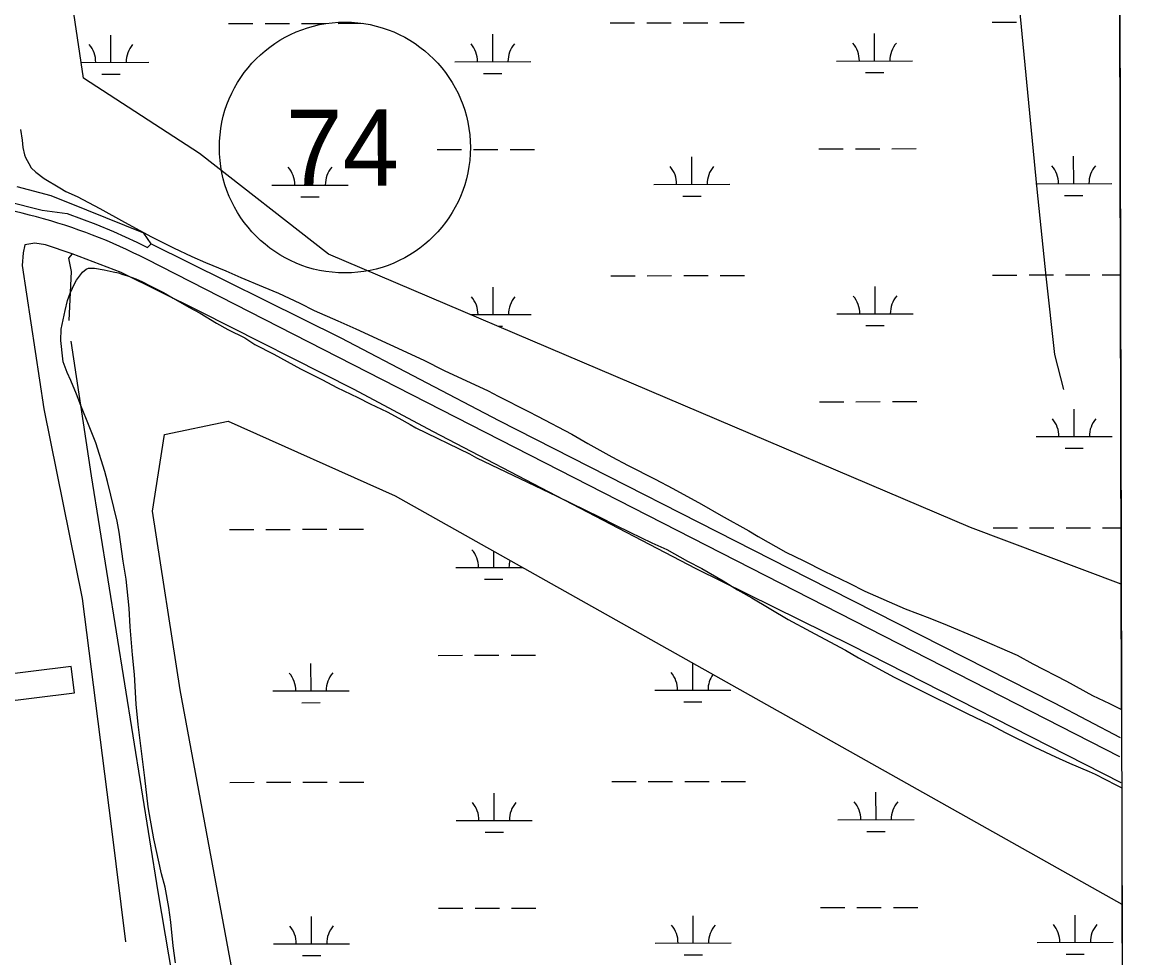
# Model space of a CAD drawing. Extents: x 3329332 to 3367211, y 631066 to 656469.
# Drawn here: x 3363578 to 3365030, y 639263 to 640494 of the extents above; entities that cross this region are included whole.
import ezdxf

# ---------------------------------------------------------------- set-up
doc = ezdxf.new("R2010")
doc.units = 0
for name, color, linetype in [('V-BLDG-OTLN', 7, 'Continuous'), ('V-GRID-FRAM', 7, 'Continuous'), ('V-ROAD-CNTR', 7, 'Continuous'), ('V-ROAD-IDEN', 7, 'Continuous'), ('V-SITE-VEGE', 7, 'Continuous'), ('V-TOPO-SHOR', 7, 'Continuous'), ('V-WETL-SWMP', 7, 'Continuous')]:
    doc.layers.add(name, color=color, linetype=linetype)

msp = doc.modelspace()

# ---------------------------------------------------------------- linework, layer by layer
at = {"layer": 'V-BLDG-OTLN'}
msp.add_lwpolyline([(3363539.6, 639633.8), (3363543.9, 639599.1), (3363646.9, 639612), (3363642.5, 639646.7)], close=True, dxfattribs=at)
at = {"layer": 'V-GRID-FRAM'}
msp.add_lwpolyline([(3333429.9, 654632), (3364987.9, 654691.7), (3365030.2, 636507.7), (3333456.4, 636448), (3333429.9, 654632)], dxfattribs=at)
at = {"layer": 'V-ROAD-CNTR'}
msp.add_lwpolyline([(3365020.7, 639527.6), (3363741.5, 640182.1)], dxfattribs=at)
msp.add_arc((3363407.1, 639530.1), 732.8, 62.8442, 87.1319, dxfattribs=at)
at = {"layer": 'V-ROAD-IDEN'}
msp.add_circle((3364002.2, 640329.1), 165, dxfattribs=at)
msp.add_circle((3364002.2, 640329.1), 165, dxfattribs=at)
at = {"layer": 'V-SITE-VEGE'}
for p, q in [((3363657.1, 640165.1), (3363662.2, 640168.9)), ((3363662.2, 640168.9), (3363665, 640170.5)), ((3363665, 640170.5), (3363672.9, 640170.3)), ((3363672.9, 640170.3), (3363685.7, 640168.4)), ((3363685.7, 640168.4), (3363697.4, 640165.4)), ((3363647.3, 640150.7), (3363649.6, 640154.6)), ((3363649.6, 640154.6), (3363657.1, 640165.1)), ((3363697.4, 640165.4), (3363704.6, 640164.1)), ((3363704.6, 640164.1), (3363710.2, 640162.3)), ((3363710.2, 640162.3), (3363716.3, 640160.5)), ((3363716.3, 640160.5), (3363727.4, 640156.4)), ((3363727.4, 640156.4), (3363736.2, 640152.3)), ((3363640.9, 640137.4), (3363647.3, 640150.7)), ((3363736.2, 640152.3), (3363746.2, 640147)), ((3363746.2, 640147), (3363763.9, 640138.3)), ((3363763.9, 640138.3), (3363776.6, 640130.8)), ((3363634.3, 640114.7), (3363637.4, 640128)), ((3363637.4, 640128), (3363640.9, 640137.4)), ((3363776.6, 640130.8), (3363797, 640119.2)), ((3363629.3, 640090.2), (3363634.3, 640114.7)), ((3363797, 640119.2), (3363812, 640111.1)), ((3363812, 640111.1), (3363833.5, 640098.3)), ((3363833.5, 640098.3), (3363848.4, 640089.6)), ((3363629, 640075.1), (3363629.3, 640090.2)), ((3363848.4, 640089.6), (3363870.5, 640078.6)), ((3363631.3, 640051), (3363629, 640075.1)), ((3363870.5, 640078.6), (3363883.8, 640069.9)), ((3363883.8, 640069.9), (3363908.7, 640057.1)), ((3363908.7, 640057.1), (3363944, 640038)), ((3363631.8, 640047.1), (3363631.3, 640051)), ((3363637.1, 640033), (3363631.8, 640047.1)), ((3363944, 640038), (3363972.8, 640023.4)), ((3363641.9, 640022.8), (3363637.1, 640033)), ((3363649.4, 640004.8), (3363641.9, 640022.8)), ((3363972.8, 640023.4), (3363991.6, 640013.5)), ((3363991.6, 640013.5), (3364019.3, 640000.1)), ((3363655.2, 639989.6), (3363649.4, 640004.8)), ((3364019.3, 640000.1), (3364035.3, 639992)), ((3363665.9, 639962.6), (3363655.2, 639989.6)), ((3364035.3, 639992), (3364058, 639981.4)), ((3364058, 639981.4), (3364073, 639973.3)), ((3364073, 639973.3), (3364087.9, 639964.6)), ((3364087.9, 639964.6), (3364095.6, 639960.6)), ((3363674.9, 639940.6), (3363665.9, 639962.6)), ((3364095.6, 639960.6), (3364165.9, 639926.2)), ((3363686.5, 639902.9), (3363674.9, 639940.6)), ((3364165.9, 639926.2), (3364175.3, 639920.9)), ((3364175.3, 639920.9), (3364281, 639870.7)), ((3363690.1, 639890), (3363686.5, 639902.9)), ((3363703, 639837.7), (3363690.1, 639890)), ((3364281, 639870.7), (3364337.5, 639842.8)), ((3363705.5, 639823.1), (3363703, 639837.7)), ((3364337.5, 639842.8), (3364357.9, 639832.3)), ((3363710.9, 639785), (3363705.5, 639823.1)), ((3364357.9, 639832.3), (3364376.8, 639823)), ((3364376.8, 639823), (3364405.5, 639809)), ((3364405.5, 639809), (3364425.5, 639800.2)), ((3364425.5, 639800.2), (3364452.6, 639785.1)), ((3363714.9, 639761.5), (3363710.9, 639785)), ((3364452.6, 639785.1), (3364471.4, 639775.2)), ((3364471.4, 639775.2), (3364499.5, 639759)), ((3363718.6, 639723.4), (3363714.9, 639761.5)), ((3364499.5, 639759), (3364518.3, 639747.4)), ((3364518.3, 639747.4), (3364537.1, 639737)), ((3364537.1, 639737), (3364585.1, 639708.1)), ((3363719.8, 639698.8), (3363718.6, 639723.4)), ((3364585.1, 639708.1), (3364614.4, 639692.4)), ((3363722.9, 639661.8), (3363719.8, 639698.8)), ((3364614.4, 639692.4), (3364633.2, 639682.5)), ((3364633.2, 639682.5), (3364660.3, 639668)), ((3363725.8, 639636.1), (3363722.9, 639661.8)), ((3364660.3, 639668), (3364677.5, 639658.1)), ((3364677.5, 639658.1), (3364724.4, 639632.6)), ((3363727.8, 639596.9), (3363725.8, 639636.1)), ((3364724.4, 639632.6), (3364753.2, 639618)), ((3364753.2, 639618), (3364820.2, 639584.8)), ((3363730.6, 639570), (3363727.8, 639596.9)), ((3364820.2, 639584.8), (3364850.6, 639570.2)), ((3363739.2, 639500), (3363730.6, 639570)), ((3364850.6, 639570.2), (3364871.1, 639559.2)), ((3364871.1, 639559.2), (3364909.3, 639540.5)), ((3364909.3, 639540.5), (3364936.4, 639527.7)), ((3364936.4, 639527.7), (3364954.7, 639519.5)), ((3364954.7, 639519.5), (3364980.7, 639508.3)), ((3363743.5, 639461.9), (3363739.2, 639500)), ((3364980.7, 639508.3), (3364988.5, 639504.8)), ((3364988.5, 639504.8), (3365015.6, 639490.9)), ((3365015.6, 639490.9), (3365023.3, 639487)), ((3365023.3, 639487), (3365030.2, 636507.7)), ((3363745.5, 639451.8), (3363743.5, 639461.9)), ((3363751, 639419.8), (3363745.5, 639451.8)), ((3363761.2, 639373.8), (3363751, 639419.8)), ((3363765.9, 639356.4), (3363761.2, 639373.8)), ((3363771, 639329.4), (3363765.9, 639356.4)), ((3363773.4, 639310.4), (3363771, 639329.4)), ((3363776.6, 639279), (3363773.4, 639310.4)), ((3363779.5, 639256.6), (3363776.6, 639279))]:
    msp.add_line(p, q, dxfattribs=at)
for points in [[(3365023, 639590.1), (3365016.6, 642361.5), (3364994, 642372.5), (3364958.7, 642392.2), (3364915.6, 642417.7), (3364886.3, 642435.6)], [(3363576, 640352.8), (3363577.9, 640338.8), (3363578.8, 640329.3), (3363580.9, 640319.7), (3363582.5, 640315.8), (3363586.8, 640307.9), (3363590, 640302.2), (3363596.1, 640296.5), (3363607.1, 640288.5), (3363627.5, 640276.3), (3363635.2, 640271.1), (3363650.2, 640264.7), (3363680.1, 640249), (3363712.7, 640231), (3363748, 640211.8), (3363776.8, 640197.3), (3363801.2, 640185.6), (3363818.9, 640178), (3363845.5, 640166.8), (3363865.4, 640158), (3363894.8, 640145.7), (3363914.8, 640137.5), (3363943, 640124.6), (3363961.8, 640114.7), (3363992.8, 640101.2), (3364016.7, 640090.7), (3364105.8, 640049.2), (3364132.9, 640035.8), (3364190.5, 640008.9), (3364203.8, 640002), (3364243.6, 639982.1), (3364255.2, 639975.8), (3364300.6, 639951.9), (3364321.6, 639939.8), (3364353.1, 639922.4), (3364374.6, 639910.7), (3364410, 639892.7), (3364433.3, 639880.5), (3364470.8, 639860.2), (3364496.8, 639845.1), (3364533.3, 639824.8), (3364545.4, 639817.3), (3364581.9, 639797), (3364605.7, 639785.3), (3364632.3, 639771.9), (3364664.9, 639756.2), (3364685.9, 639745.7), (3364738.6, 639722.3), (3364771.3, 639709.9), (3364794, 639701), (3364829.5, 639685.8), (3364886, 639661.2), (3364906.4, 639650.1), (3364950.7, 639627.4), (3364985, 639608.3), (3365007.1, 639597.8), (3365023, 639590.1)]]:
    msp.add_lwpolyline(points, dxfattribs=at)
at = {"layer": 'V-TOPO-SHOR'}
for points in [[(3363842.9, 641705.6), (3363751.5, 641522), (3363763.2, 641395.9), (3363774.9, 641315.6), (3363820.9, 641201.1), (3363855.5, 641109.4), (3363947.4, 641017.9), (3364176.8, 640972.5), (3364371.8, 640927), (3364532.4, 640881.4), (3364693, 640824.4), (3364807.9, 640687), (3364888.5, 640515.2), (3364911.8, 640274.5), (3364923.5, 640159.9), (3364935.2, 640056.7), (3364946.7, 640010.9)], [(3363557.4, 640258.4), (3363604.4, 640246.8), (3363637.2, 640242.2), (3363674.7, 640228.2), (3363698.2, 640218.8), (3363728.7, 640204.8), (3363742.8, 640197.8), (3363747.5, 640202.5), (3363738.1, 640216.6), (3363663, 640246.9), (3363616, 640265.6), (3363571.5, 640277.2)], [(3363643.7, 640189.4), (3363608.5, 640201.1), (3363594.5, 640203.4), (3363581.6, 640201), (3363579.3, 640190.5), (3363578.1, 640174.1), (3363606.6, 639985.4)], [(3363747.5, 640202.5), (3363996.9, 640078.7), (3364204.6, 639970.1), (3364610.6, 639763.3), (3364934.5, 639598.6), (3365021.4, 639553.1)], [(3365022.7, 639493.3), (3364668.3, 639674.3), (3364464.1, 639774.8), (3364117.8, 639955.8), (3364014.6, 640010.8), (3363811.5, 640113.5), (3363708.3, 640164.9), (3363643.7, 640189.4), (3363639.1, 640183.6), (3363642.6, 640166), (3363639.2, 640101.5)], [(3364077.4, 637523.9), (3363955.4, 638180.4), (3363913.4, 638425.6), (3363756.9, 639350), (3363669, 639897.1), (3363642.3, 640074.4)], [(3363606.6, 639985.4), (3363656.7, 639736), (3363695.1, 639436.5), (3363713.8, 639284.3)]]:
    msp.add_lwpolyline(points, dxfattribs=at)
at = {"layer": 'V-WETL-SWMP'}
for p, q in [((3365016.6, 642324.6), (3365022.6, 639754.6)), ((3363658.7, 640420.2), (3363604, 640788.8)), ((3363849.2, 640492.1), (3363881.2, 640492.2)), ((3363897.2, 640492.2), (3363929.2, 640492.3)), ((3363945.2, 640492.3), (3363977.2, 640492.4)), ((3363993.2, 640492.4), (3364025.2, 640492.5)), ((3364351.1, 640493.1), (3364383.1, 640493.1)), ((3364399.1, 640493.2), (3364431.1, 640493.2)), ((3364447.1, 640493.3), (3364479.1, 640493.3)), ((3364495.1, 640493.4), (3364527.1, 640493.4)), ((3364853, 640494), (3364885, 640494.1)), ((3363694.7, 640441.1), (3363694.6, 640477.1)), ((3364196.6, 640442.1), (3364196.5, 640478.1)), ((3364698.5, 640443), (3364698.4, 640479)), ((3363655.6, 640441), (3363744.7, 640441.2)), ((3364146.6, 640442), (3364246.6, 640442.1)), ((3364648.5, 640442.9), (3364748.5, 640443.1)), ((3363811, 640321.2), (3363658.7, 640420.2)), ((3363682.7, 640425.7), (3363706.7, 640425.7)), ((3364184.6, 640426.6), (3364208.6, 640426.6)), ((3364686.5, 640427.6), (3364710.5, 640427.6)), ((3364625.3, 640327.4), (3364657.3, 640327.5)), ((3364673.3, 640327.5), (3364705.3, 640327.6)), ((3364721.3, 640327.6), (3364753.3, 640327.7)), ((3363980.5, 640188.9), (3363811, 640321.2)), ((3363956.4, 640279.7), (3363956.4, 640315.7)), ((3364123.4, 640326.5), (3364155.4, 640326.5)), ((3364171.4, 640326.6), (3364203.4, 640326.6)), ((3364219.4, 640326.7), (3364251.4, 640326.7)), ((3364458.3, 640280.7), (3364458.3, 640316.7)), ((3364960.3, 640281.6), (3364960.2, 640317.6)), ((3363906.4, 640279.6), (3364006.4, 640279.8)), ((3364408.3, 640280.6), (3364508.3, 640280.8)), ((3364910.3, 640281.5), (3365010.3, 640281.7)), ((3363944.5, 640264.3), (3363968.5, 640264.3)), ((3364446.4, 640265.2), (3364470.4, 640265.3)), ((3364948.3, 640266.2), (3364972.3, 640266.2)), ((3364824.6, 639829.4), (3363980.5, 640188.9)), ((3364351.7, 640160.4), (3364383.7, 640160.5)), ((3364399.7, 640160.5), (3364431.7, 640160.6)), ((3364447.7, 640160.6), (3364479.7, 640160.7)), ((3364495.7, 640160.7), (3364527.7, 640160.7)), ((3364853.6, 640161.4), (3364885.6, 640161.4)), ((3364901.6, 640161.5), (3364933.6, 640161.5)), ((3364949.6, 640161.5), (3364981.6, 640161.6)), ((3364997.6, 640161.6), (3365021.7, 640161.7)), ((3364197.2, 640109.4), (3364197.2, 640145.4)), ((3364699.1, 640110.3), (3364699.1, 640146.3)), ((3364167.4, 640109.3), (3364247.2, 640109.5)), ((3364649.1, 640110.2), (3364749.1, 640110.4)), ((3364687.2, 640094.9), (3364711.2, 640094.9)), ((3364203.5, 640094), (3364209.3, 640094)), ((3364626, 639994.8), (3364658, 639994.8)), ((3364674, 639994.8), (3364706, 639994.9)), ((3364722, 639994.9), (3364754, 639995)), ((3364960.9, 639949), (3364960.8, 639985)), ((3363764.9, 639951.5), (3363848.7, 639969.2)), ((3363848.7, 639969.2), (3364068.2, 639871.1)), ((3363749.2, 639850.6), (3363764.9, 639951.5)), ((3364910.9, 639948.9), (3365010.9, 639949.1)), ((3364948.9, 639933.5), (3364972.9, 639933.6)), ((3364068.2, 639871.1), (3365023.6, 639333.8)), ((3363785.5, 639616), (3363749.2, 639850.6)), ((3363850.5, 639826.8), (3363882.5, 639826.9)), ((3363898.5, 639826.9), (3363930.5, 639826.9)), ((3363946.5, 639827), (3363978.5, 639827)), ((3363994.5, 639827.1), (3364026.5, 639827.1)), ((3365022.6, 639754.6), (3364824.6, 639829.4)), ((3364854.3, 639828.7), (3364886.3, 639828.7)), ((3364902.3, 639828.8), (3364934.3, 639828.8)), ((3364950.3, 639828.9), (3364982.3, 639828.9)), ((3364998.3, 639829), (3365022.5, 639829)), ((3364197.9, 639776.7), (3364197.8, 639798.1)), ((3364147.9, 639776.6), (3364235.8, 639776.8)), ((3364185.9, 639761.3), (3364209.9, 639761.3)), ((3364124.7, 639661.1), (3364156.7, 639661.2)), ((3364172.7, 639661.2), (3364204.7, 639661.3)), ((3364220.7, 639661.3), (3364252.7, 639661.4)), ((3363957.7, 639614.4), (3363957.6, 639650.4)), ((3364459.6, 639615.3), (3364459.5, 639651)), ((3364161.7, 637589.5), (3363785.5, 639616)), ((3363907.7, 639614.3), (3364007.7, 639614.5)), ((3364409.6, 639615.2), (3364509.6, 639615.4)), ((3363945.7, 639598.9), (3363969.7, 639599)), ((3364447.6, 639599.9), (3364471.6, 639599.9)), ((3363851.1, 639494.1), (3363883.1, 639494.2)), ((3363899.1, 639494.2), (3363931.1, 639494.3)), ((3363947.1, 639494.3), (3363979.1, 639494.4)), ((3363995.1, 639494.4), (3364027.1, 639494.5)), ((3364353, 639495.1), (3364385, 639495.1)), ((3364401, 639495.2), (3364433, 639495.2)), ((3364449, 639495.2), (3364481, 639495.3)), ((3364497, 639495.3), (3364529, 639495.4)), ((3364198.5, 639444), (3364198.4, 639480)), ((3364700.4, 639445), (3364700.3, 639481)), ((3364148.5, 639443.9), (3364248.5, 639444.1)), ((3364650.4, 639444.9), (3364750.4, 639445.1)), ((3364186.5, 639428.6), (3364210.5, 639428.6)), ((3364688.4, 639429.5), (3364712.4, 639429.6)), ((3364125.3, 639328.5), (3364157.3, 639328.5)), ((3364173.3, 639328.6), (3364205.3, 639328.6)), ((3364221.3, 639328.6), (3364253.3, 639328.7)), ((3364627.2, 639329.4), (3364659.2, 639329.5)), ((3364675.2, 639329.5), (3364707.2, 639329.6)), ((3364723.2, 639329.6), (3364755.2, 639329.7)), ((3365023.6, 639333.8), (3365027.7, 637566)), ((3363958.3, 639281.7), (3363958.3, 639317.7)), ((3364460.2, 639282.7), (3364460.2, 639318.7)), ((3364962.1, 639283.6), (3364962.1, 639319.6)), ((3363908.3, 639281.6), (3364008.3, 639281.8)), ((3364410.2, 639282.6), (3364510.2, 639282.8)), ((3364912.1, 639283.5), (3365012.1, 639283.7)), ((3364448.3, 639267.2), (3364472.3, 639267.3)), ((3364950.2, 639268.2), (3364974.2, 639268.2)), ((3363946.4, 639266.3), (3363970.4, 639266.3))]:
    msp.add_line(p, q, dxfattribs=at)
for centre, start, end in [((3363639.5, 640441.5), 359.3365, 40.8801), ((3363749.9, 640441.7), 139.3365, 180.8801), ((3364141.4, 640442.4), 359.3365, 40.8801), ((3364251.8, 640442.6), 139.3365, 180.8801), ((3364643.3, 640443.4), 359.3365, 40.8801), ((3364753.8, 640443.6), 139.3365, 180.8801), ((3363901.2, 640280.1), 359.3365, 40.8801), ((3364011.7, 640280.3), 139.3365, 180.8801), ((3364403.1, 640281.1), 359.3365, 40.8801), ((3364513.6, 640281.3), 139.3365, 180.8801), ((3364905, 640282), 359.3365, 40.8801), ((3365015.5, 640282.2), 139.3365, 180.8801), ((3364142, 640109.8), 359.3365, 40.8801), ((3364252.5, 640110), 139.3365, 180.8801), ((3364643.9, 640110.7), 359.3365, 40.8801), ((3364754.4, 640110.9), 139.3365, 180.8801), ((3364905.6, 639949.3), 359.3365, 40.8801), ((3365016.1, 639949.5), 139.3365, 180.8801), ((3364142.6, 639777.1), 359.3365, 40.8801), ((3364253.1, 639777.3), 165.3108, 180.8801), ((3363902.5, 639614.8), 359.3365, 40.8801), ((3364012.9, 639615), 139.3365, 180.8801), ((3364404.4, 639615.7), 359.3365, 40.8801), ((3364514.8, 639615.9), 145.0468, 180.8801), ((3364143.2, 639444.4), 359.3365, 40.8801), ((3364253.7, 639444.6), 139.3365, 180.8801), ((3364645.2, 639445.4), 359.3365, 40.8801), ((3364755.6, 639445.6), 139.3365, 180.8801), ((3363903.1, 639282.1), 359.3365, 40.8801), ((3364013.6, 639282.3), 139.3365, 180.8801), ((3364405, 639283), 359.3365, 40.8801), ((3364515.5, 639283.2), 139.3365, 180.8801), ((3364906.9, 639284), 359.3365, 40.8801), ((3365017.4, 639284.2), 139.3365, 180.8801)]:
    msp.add_arc(centre, 35.2, start, end, dxfattribs=at)

# ---------------------------------------------------------------- texts
at = {"layer": 'V-ROAD-IDEN'}
msp.add_text('74', height=100, rotation=0.1083, dxfattribs=at).set_placement((3363924.8, 640278.9))

doc.saveas('drawing.dxf')
